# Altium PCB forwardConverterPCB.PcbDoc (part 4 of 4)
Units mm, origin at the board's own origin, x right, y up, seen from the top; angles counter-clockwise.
Board outline 382.81 x 370.12 mm, 8 copper layers (L1, L2 (GND), L3, L4, L5(GND), L6, L7 (GND), L8), stack 1.028 mm thick; 352 components, 187 nets, 1188 pads, 1016 vias.
Unrouted connection lines stored in the file: 19.
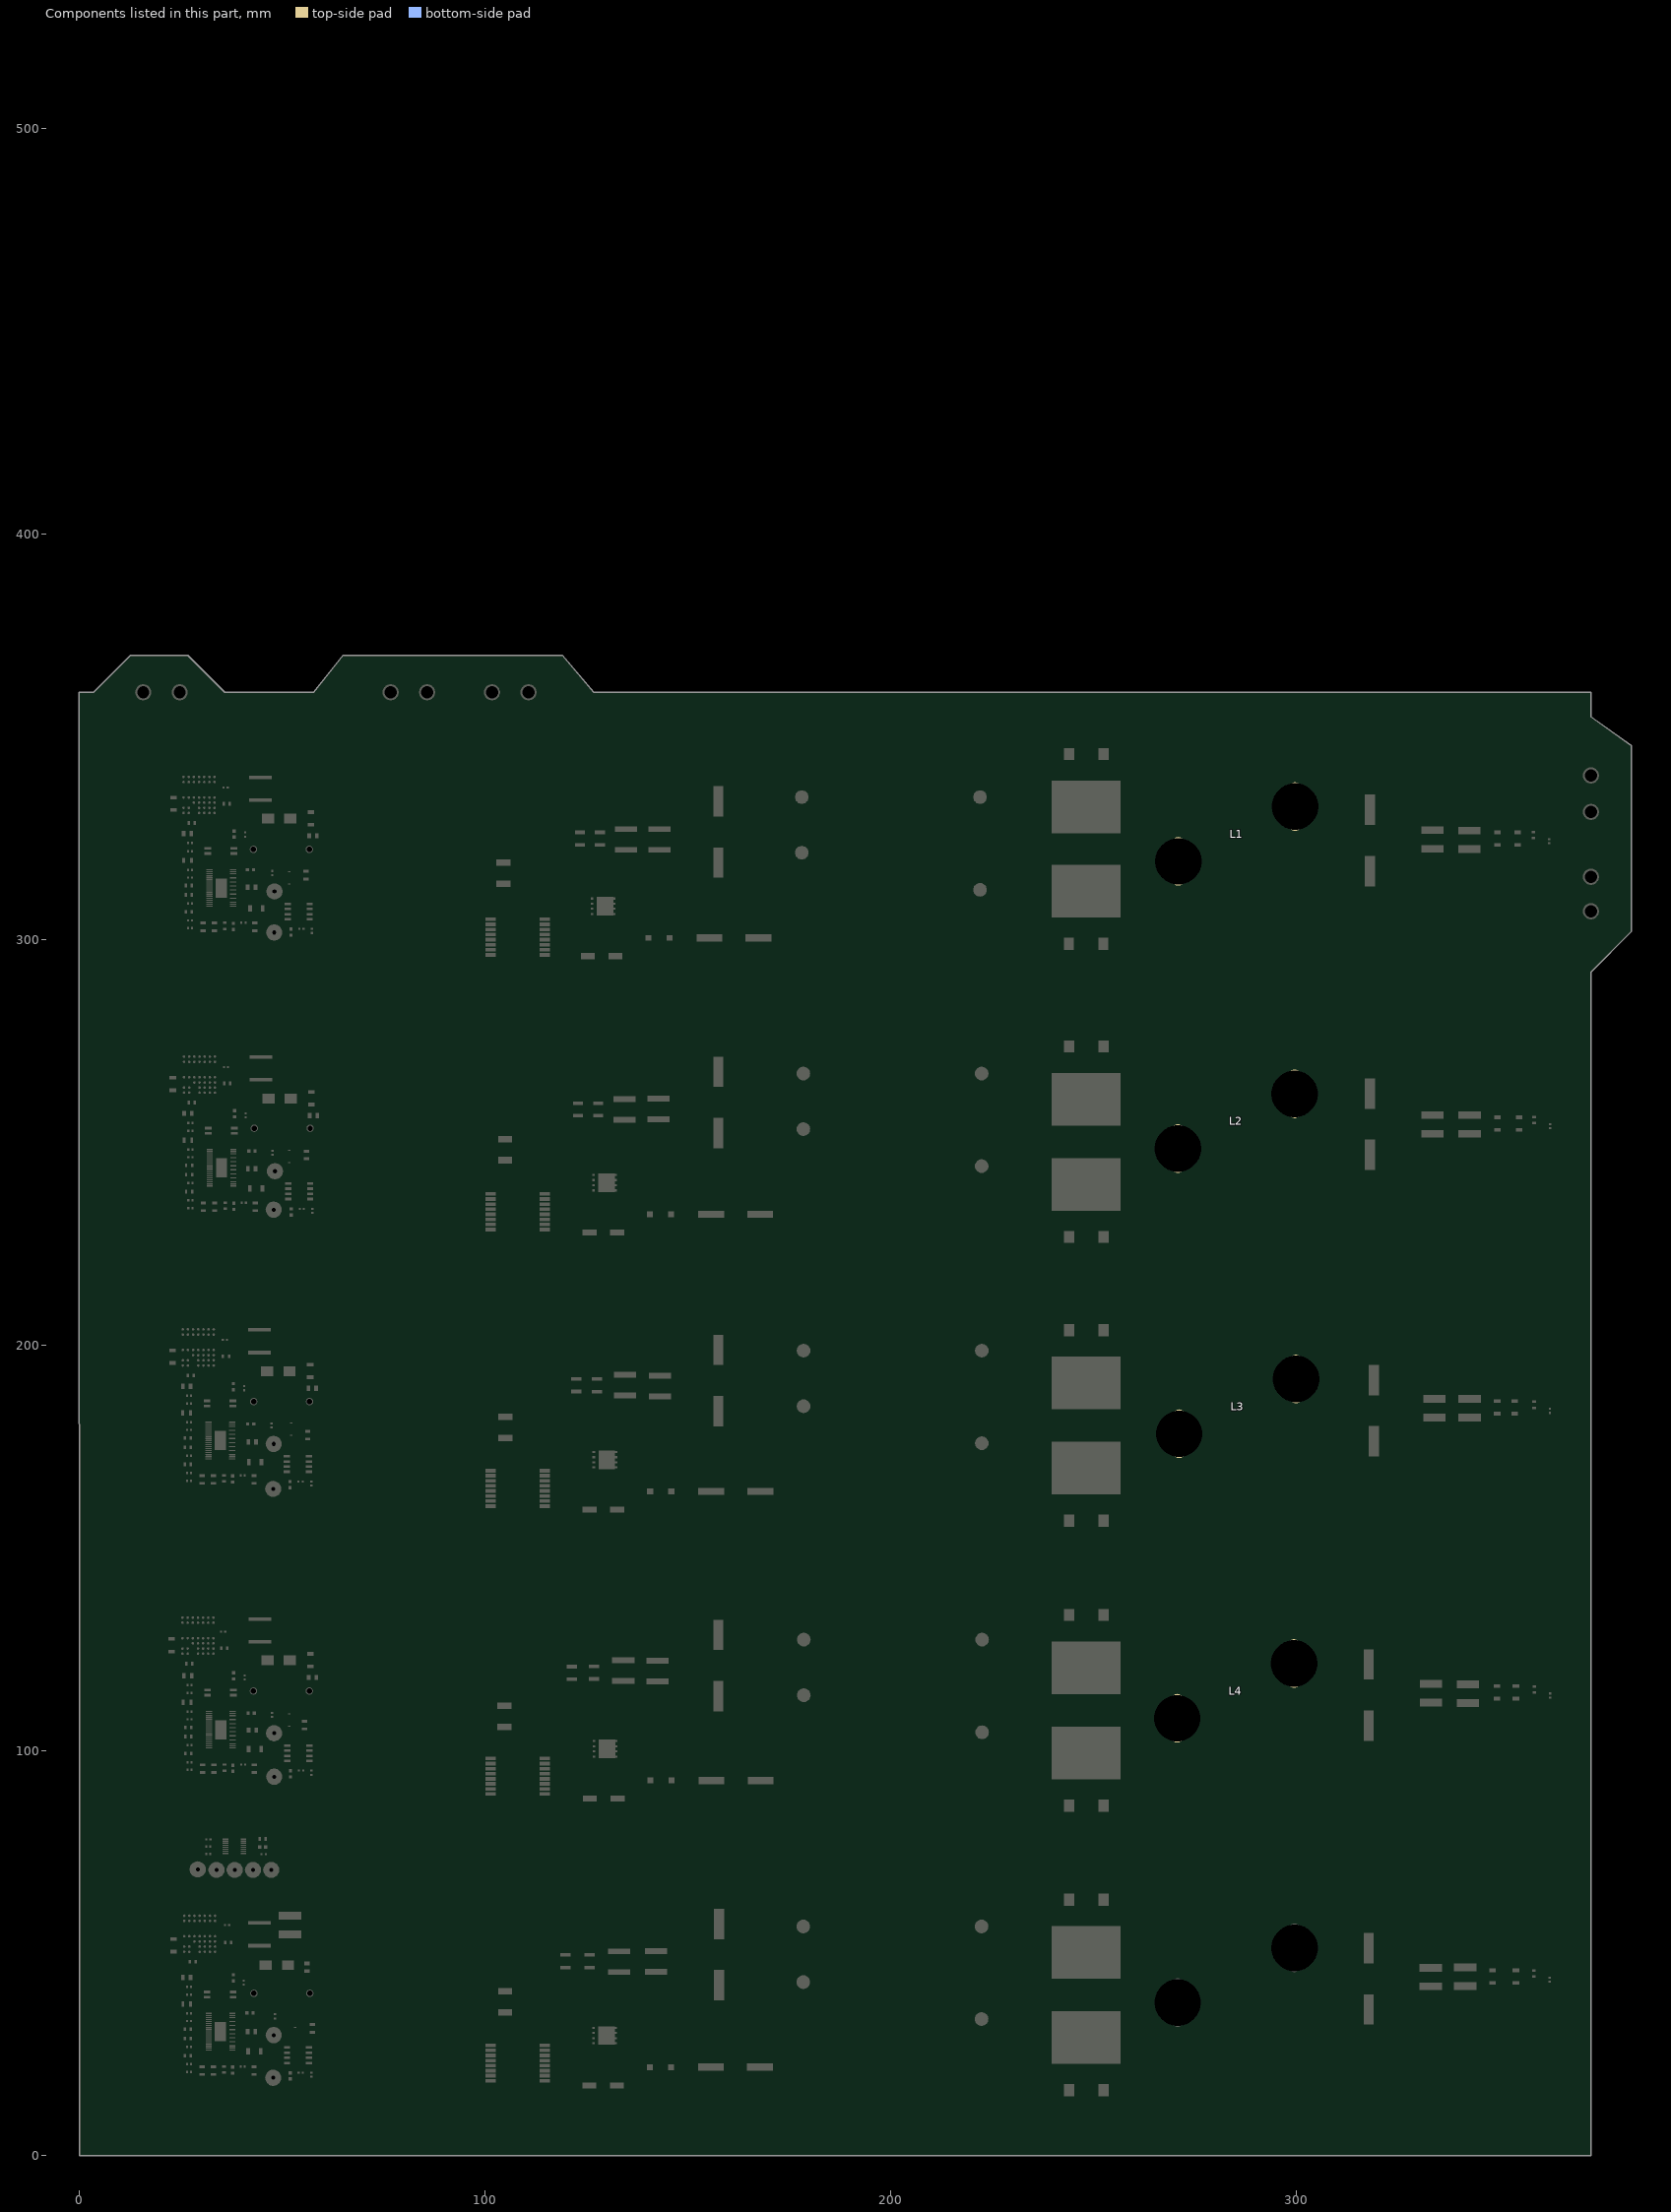
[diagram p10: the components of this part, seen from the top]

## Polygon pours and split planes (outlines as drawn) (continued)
NetNMOS2_1 on L1 "NETNMOS2_1_L01_P316" (solid, pour order 316): 97.95,245.75 99.2,247 109.2,247 110.2,245.75 106.688,235.744 106.688,229.794 105.888,228.994 98.962,228.994 97.95,230.006
NetC23_2 on L1 "NETC23_2_L01_P277" (solid, pour order 277): 31.452,340.273 31.802,340.623 33.452,340.623 33.777,340.223 33.777,338.648 33.452,338.323 31.802,338.323 31.452,338.673
no net on L1 "NONET_L01_P271" (solid, pour order 271): 103.577,330.723 103.077,330.723
NetC121_1 on L1 "NETC121_1_L01_P269" (solid, pour order 269): 143.196,26.318 143.946,27.068 159.446,27.068 160.196,26.318 160.196,17.318 159.446,16.568 143.946,16.568 143.196,17.318
NetC11_1 on L1 "NETC11_1_L01_P265" (solid, pour order 265): 142.825,304.875 143.575,305.625 159.075,305.625 159.825,304.875 159.825,295.875 159.075,295.125 143.575,295.125 142.825,295.875
GND on L1 "L1-+PH2" (solid, pour order 352): 257.95,62.549 257.95,71.551 256.2,73.5 218,73.5 216.051,71.551 216.102,45.5 218,44.049 227.401,44.049 228.852,45.5 228.852,58.75 230.901,60.799 256.2,60.799
+PH5 on L1 "L1-+PH2" (solid, pour order 349): 257.7,132.749 257.7,142 255.95,143.898 217.75,143.898 215.852,142 215.852,115.7 217.75,114.249 227.151,114.249 228.602,115.7 228.602,128.95 230.651,130.999 255.95,130.999
+PH4 on L1 "L1-+PH2" (solid, pour order 346): 257.75,202.949 257.749,212.5 256,214.249 217.651,214.249 215.902,212.5 215.902,185.9 217.8,184.449 227.201,184.449 228.652,185.9 228.652,199.15 230.701,201.199 256,201.199
+PH3 on L1 "L1-+PH2" (solid, pour order 344): 257.95,273.049 257.95,283.651 255.95,285.55 218,285.55 216.102,283.651 216.102,256 218,254.549 227.401,254.549 228.852,256 228.852,269.25 230.901,271.299 256.2,271.299
+PH2 on L1 "L1-+PH2" (solid, pour order 321): 257.95,345.25 257.95,353.901 255.95,355.8 218,355.8 216.102,353.901 216.2,326 217.7,324.5 227.45,324.5 228.7,326 228.852,341.152 230.95,343.25 255.95,343.25
NetD1_1 on L1 "L1-+PH2" (solid, pour order 320): 257.7,299.75 257.7,291.099 255.7,289.2 217.75,289.2 215.852,291.099 215.852,319.25 217.75,321.148 227.2,321.148 228.649,319.699 228.602,303.848 230.7,301.75 255.7,301.75
NetD17_1 on L1 "L1-+PH2" (solid, pour order 303): 257.85,17 257.85,8.349 255.85,6.45 217.9,6.45 216.002,8.349 216.002,38.848 218.002,40.848 227.2,40.848 228.752,39.296 228.752,21.098 230.85,19 255.85,19
NetD13_1 on L1 "L1-+PH2" (solid, pour order 302): 257.6,87.2 257.6,78.549 255.6,76.65 217.65,76.65 215.752,78.549 215.752,109.048 217.752,111.048 226.95,111.048 228.502,109.496 228.502,91.298 230.6,89.2 255.6,89.2
NetD9_1 on L1 "L1-+PH2" (solid, pour order 301): 257.65,157.4 257.65,148.749 255.65,146.85 217.7,146.85 215.802,148.749 215.802,179.248 217.802,181.248 227,181.248 228.552,179.696 228.552,161.498 230.65,159.4 255.65,159.4
NetD5_1 on L1 "L1-+PH2" (solid, pour order 300): 257.85,227.5 257.85,219.129 255.85,217.129 218.002,217.129 216.002,219.129 216.002,249.348 218.002,251.348 227.2,251.348 228.752,249.796 228.752,231.598 230.85,229.5 255.85,229.5
GND on L3 "L1-NetC2_1" (solid, pour order 1176): 296.696,23.648 281.161,23.405 275.28,17.686 275.28,2.233 277.475,0.537 364.35,0.537 365.95,2.137 365.95,41.238 363.946,43.242 298.7,43.242 296.696,41.238
+PH5 on L3 "L1-+PH5" (solid, pour order 1159): 296.525,47.408 298.704,45.229 363.696,45.229 365.7,47.233 365.7,111.174 363.696,113.178 363.641,113.178 363.573,113.246 298.327,113.246 296.525,111.444
+PH4 on L3 "L1-+PH4" (solid, pour order 1158): 346.834,115.229 363.702,115.108 365.706,117.112 365.706,181.485 363.702,183.49 347.702,183.49 347.7,183.487 298.2,183.487 296.196,181.483 296.196,165.483 296.196,117.36 298.327,115.229
+PH3 on L3 "L1-+PH3" (solid, pour order 1157): 346.016,185.483 363.452,185.358 365.456,187.363 365.456,251.735 363.452,253.74 298.202,253.74 296.198,251.735 296.198,235.735 296.198,203.49 296.196,203.488 296.196,187.487 298.2,185.483
+PH2 on L3 "L1-+PH2 1" (solid, pour order 1156): 363.446,255.608 363.452,255.608 365.456,257.612 365.456,321.985 363.452,323.99 363.448,323.99 298.202,323.99 296.198,321.985 296.198,305.985 296.197,273.614 296.196,273.613 296.196,257.612 298.2,255.608
NetC2_1 on L3 "L1-NetC2_1" (solid, pour order 1154): 296.196,327.863 298.2,325.858 373.696,325.858 375.7,327.863 375.7,345.417 365.425,355.692 298.2,355.692 296.196,353.687
NetD17_4 on L3 "NETD17_4_L03_P1129" (solid, pour order 1129): 236.138,56.376 238.15,58.387 271.624,58.387 274.099,56.376 274.099,23.683 271.624,21.382 237.844,21.382 236.138,23.088
NetD13_4 on L3 "NETD13_4_L03_P1128" (solid, pour order 1128): 235.888,126.576 237.9,128.587 271.374,128.587 273.849,126.576 273.849,93.883 271.374,91.582 237.594,91.582 235.888,93.287
NetD9_4 on L3 "NETD9_4_L03_P1127" (solid, pour order 1127): 235.938,196.776 237.95,198.787 271.424,198.787 273.899,196.776 273.899,164.083 271.424,161.782 237.644,161.782 235.938,163.487
NetD5_4 on L3 "NETD5_4_L03_P1126" (solid, pour order 1126): 236.139,266.907 238.151,268.918 271.625,268.918 274.1,266.907 274.1,234.214 271.625,231.912 237.845,231.912 236.139,233.618
NetD1_4 on L3 "NETD1_4_L03_P1125" (solid, pour order 1125): 235.914,339.082 237.926,341.093 271.4,341.093 273.875,339.082 273.875,306.389 271.4,304.087 237.62,304.087 235.914,305.793
GND on L3 "GND_L03_P623" (solid, pour order 623): 98.115,188.138 99.115,189.138 169.4,189.138 170.265,188.138 170.265,182.32 166.365,177.37 127.946,177.383 127.254,176.692 127.254,170.351 126.994,169.991 123.232,169.991 114.982,180.37 99.115,180.37 98.115,181.37
NetC121_2 on L3 "L3-NetC121_2" (solid, pour order 1101): 19 vertices, not listed, extent 111.208,8.056 182.283,45.406
NetC98_2 on L3 "L3-NetC98_2" (solid, pour order 1099): 19 vertices, not listed, extent 111.336,78.79 182.411,116.14
NetC75_2 on L3 "L3-NetC75_2" (solid, pour order 1097): 19 vertices, not listed, extent 111.282,150.079 182.357,187.429
NetC52_2 on L3 "L3-NetC52_2" (solid, pour order 1095): 19 vertices, not listed, extent 111.223,218.427 182.298,255.777
NetC11_2 on L3 "L3-NetC11_2" (solid, pour order 1093): 19 vertices, not listed, extent 110.839,286.61 181.914,323.96
+12V on L3 "L1-+12V" (solid, pour order 1061): 51 vertices, not listed, extent 5.95,5.219 27.7,364.487
Vin on L3 "L1-No Net" (solid, pour order 1060): 49 vertices, not listed, extent 65.009,5.28 186.969,364.487
GND on L3 "GND_L03_P624" (solid, pour order 624): 98.365,256.137 99.365,257.137 169.65,257.137 170.515,256.137 170.515,250.32 166.615,245.37 128.196,245.383 127.504,244.692 127.504,238.351 127.244,237.991 123.482,237.991 115.232,248.37 99.365,248.37 98.365,249.37
GND on L3 "GND_L03_P622" (solid, pour order 622): 98.115,117.138 99.115,118.138 169.4,118.138 170.265,117.138 170.265,111.32 166.365,106.37 127.946,106.383 127.254,105.692 127.254,99.351 126.994,98.991 123.232,98.991 114.982,109.37 99.115,109.37 98.115,110.37
GND on L3 "GND_L03_P621" (solid, pour order 621): 98.115,46.387 99.115,47.387 169.4,47.387 170.265,46.387 170.265,40.57 166.365,35.62 127.946,35.633 127.254,34.942 127.254,28.601 126.994,28.241 123.232,28.241 114.982,38.62 99.115,38.62 98.115,39.62
NetC122_1 on L3 "NETC122_1_L03_P620" (solid, pour order 620): 127.669,32.806 128.269,33.556 134.696,33.556 141.446,33.556 142.196,32.806 142.196,24.556 142.196,15.806 141.696,15.306 130.696,15.306 130.196,15.806 130.196,17.806 130.196,22.056 127.669,25.533
NetC99_1 on L3 "NETC99_1_L03_P619" (solid, pour order 619): 127.797,103.54 128.397,104.29 134.824,104.29 141.574,104.29 142.324,103.54 142.324,95.29 142.324,86.54 141.824,86.04 130.824,86.04 130.324,86.54 130.324,88.54 130.324,92.79 127.797,96.268
NetC98_1 on L3 "NETC98_1_L03_P618" (solid, pour order 618): 143.324,97.04 144.074,97.79 159.574,97.79 160.324,97.04 160.324,88.04 159.574,87.29 144.074,87.29 143.324,88.04
NetC76_1 on L3 "NETC76_1_L03_P617" (solid, pour order 617): 127.743,174.829 128.343,175.579 134.77,175.579 141.52,175.579 142.27,174.829 142.27,166.579 142.27,157.829 141.77,157.329 130.77,157.329 130.27,157.829 130.27,159.829 130.27,164.079 127.743,167.557
NetC75_1 on L3 "NETC75_1_L03_P616" (solid, pour order 616): 143.27,168.329 144.02,169.079 159.52,169.079 160.27,168.329 160.27,159.329 159.52,158.579 144.02,158.579 143.27,159.329
NetC53_1 on L3 "NETC53_1_L03_P615" (solid, pour order 615): 127.684,243.177 128.284,243.927 134.711,243.927 141.461,243.927 142.211,243.177 142.211,234.927 142.211,226.177 141.711,225.677 130.711,225.677 130.211,226.177 130.211,228.177 130.211,232.427 127.684,235.905
NetC52_1 on L3 "NETC52_1_L03_P609" (solid, pour order 609): 143.211,236.677 143.961,237.427 159.461,237.427 160.211,236.677 160.211,227.677 159.461,226.927 143.961,226.927 143.211,227.677
NetNMOS5_1 on L3 "NETNMOS5_1_L03_P596" (solid, pour order 596): 97.7,35.987 98.95,37.237 108.95,37.237 109.95,35.987 106.437,25.981 106.437,20.031 105.638,19.231 98.712,19.231 97.7,20.244
NetNMOS4_1 on L3 "NETNMOS4_1_L03_P595" (solid, pour order 595): 97.7,106.738 98.95,107.987 108.95,107.987 109.95,106.738 106.437,96.731 106.437,90.781 105.638,89.981 98.712,89.981 97.7,90.994
NetNMOS3_1 on L3 "NETNMOS3_1_L03_P594" (solid, pour order 594): 97.7,177.738 98.95,178.987 108.95,178.987 109.95,177.738 106.437,167.731 106.437,161.781 105.638,160.981 98.712,160.981 97.7,161.994
NetNMOS2_1 on L3 "NETNMOS2_1_L03_P593" (solid, pour order 593): 97.95,245.737 99.2,246.987 109.2,246.987 110.2,245.737 106.687,235.731 106.687,229.781 105.888,228.981 98.962,228.981 97.95,229.994
GND on L3 "GND_L03_P582" (solid, pour order 582): 97.769,323.275 98.769,324.275 168.919,324.275 169.919,323.275 169.919,319.225 166.019,314.275 127.6,314.287 126.909,313.596 126.909,307.255 126.649,306.895 122.886,306.895 114.636,317.275 98.769,317.275 97.769,318.275
NetC12_1 on L3 "NETC12_1_L03_P581" (solid, pour order 581): 127.3,311.36 127.9,312.11 134.327,312.11 141.077,312.11 141.827,311.36 141.827,303.11 141.827,294.36 141.327,293.86 130.327,293.86 129.827,294.36 129.827,296.36 129.827,300.61 127.3,304.087
no net on L3 "NONET_L03_P575" (solid, pour order 575): 103.577,330.71 103.077,330.71
NetC121_1 on L3 "NETC121_1_L03_P573" (solid, pour order 573): 143.196,26.306 143.946,27.056 159.446,27.056 160.196,26.306 160.196,17.306 159.446,16.556 143.946,16.556 143.196,17.306
NetC11_1 on L3 "NETC11_1_L03_P572" (solid, pour order 572): 142.827,304.86 143.577,305.61 159.077,305.61 159.827,304.86 159.827,295.86 159.077,295.11 143.577,295.11 142.827,295.86
NetNMOS1_1 on L3 "NETNMOS1_1_L03_P571" (solid, pour order 571): 97.95,313.738 99.2,314.987 109.2,314.987 110.2,313.738 106.687,303.731 106.687,297.781 105.888,296.981 98.962,296.981 97.95,297.994
GND on L3 "L1-+PH2" (solid, pour order 604): 257.95,62.537 257.95,71.538 256.2,73.487 218,73.487 216.051,71.538 216.102,45.487 218,44.037 227.401,44.037 228.852,45.487 228.852,58.737 230.901,60.787 256.2,60.787
+PH5 on L3 "L1-+PH2" (solid, pour order 603): 257.7,132.737 257.7,141.987 255.95,143.886 217.75,143.886 215.852,141.987 215.852,115.688 217.75,114.237 227.151,114.237 228.602,115.688 228.602,128.937 230.651,130.987 255.95,130.987
+PH4 on L3 "L1-+PH2" (solid, pour order 602): 257.75,202.937 257.749,212.487 256,214.236 217.651,214.236 215.902,212.487 215.902,185.887 217.8,184.437 227.201,184.437 228.652,185.887 228.652,199.137 230.701,201.187 256,201.187
+PH3 on L3 "L1-+PH2" (solid, pour order 601): 257.95,273.037 257.95,283.639 255.95,285.537 218,285.537 216.102,283.639 216.102,255.987 218,254.537 227.401,254.537 228.852,255.987 228.852,269.237 230.901,271.287 256.2,271.287
+PH2 on L3 "L1-+PH2" (solid, pour order 598): 257.95,345.237 257.95,353.889 255.95,355.787 218,355.787 216.102,353.889 216.2,325.987 217.7,324.487 227.45,324.487 228.7,325.987 228.852,341.139 230.95,343.237 255.95,343.237
NetD1_1 on L3 "L1-+PH2" (solid, pour order 597): 257.7,299.738 257.7,291.086 255.7,289.188 217.75,289.188 215.852,291.086 215.852,319.237 217.75,321.136 227.2,321.136 228.649,319.687 228.602,303.836 230.7,301.737 255.7,301.737
NetD17_1 on L3 "L1-+PH2" (solid, pour order 592): 257.85,16.987 257.85,8.336 255.85,6.438 217.9,6.438 216.002,8.336 216.002,38.835 218.002,40.835 227.2,40.835 228.752,39.284 228.752,21.086 230.85,18.987 255.85,18.987
NetD13_1 on L3 "L1-+PH2" (solid, pour order 591): 257.6,87.187 257.6,78.536 255.6,76.638 217.65,76.638 215.752,78.536 215.752,109.035 217.752,111.035 226.95,111.035 228.502,109.484 228.502,91.286 230.6,89.187 255.6,89.187
NetD9_1 on L3 "L1-+PH2" (solid, pour order 590): 257.65,157.387 257.65,148.736 255.65,146.838 217.7,146.838 215.802,148.736 215.802,179.235 217.802,181.235 227,181.235 228.552,179.684 228.552,161.486 230.65,159.387 255.65,159.387
NetD5_1 on L3 "L1-+PH2" (solid, pour order 589): 257.85,227.487 257.85,219.117 255.85,217.117 218.002,217.117 216.002,219.117 216.002,249.335 218.002,251.335 227.2,251.335 228.752,249.784 228.752,231.586 230.85,229.487 255.85,229.487
GND on L4 "L1-NetC2_1" (solid, pour order 1177): 296.696,23.648 281.161,23.405 275.28,17.686 275.28,2.233 277.475,0.537 364.35,0.537 365.95,2.137 365.95,41.238 363.946,43.242 298.7,43.242 296.696,41.238
+PH5 on L4 "L1-+PH5" (solid, pour order 1165): 296.525,47.408 298.704,45.229 363.696,45.229 365.7,47.233 365.7,111.174 363.696,113.178 363.641,113.178 363.573,113.246 298.327,113.246 296.525,111.444
+PH4 on L4 "L1-+PH4" (solid, pour order 1164): 346.834,115.229 363.702,115.108 365.706,117.112 365.706,181.485 363.702,183.49 347.702,183.49 347.7,183.487 298.2,183.487 296.196,181.483 296.196,165.483 296.196,117.36 298.327,115.229
+PH3 on L4 "L1-+PH3" (solid, pour order 1163): 346.016,185.483 363.452,185.358 365.456,187.363 365.456,251.735 363.452,253.74 298.202,253.74 296.198,251.735 296.198,235.735 296.198,203.49 296.196,203.488 296.196,187.487 298.2,185.483
+PH2 on L4 "L1-+PH2 1" (solid, pour order 1162): 363.446,255.608 363.452,255.608 365.456,257.612 365.456,321.985 363.452,323.99 363.448,323.99 298.202,323.99 296.198,321.985 296.198,305.985 296.197,273.614 296.196,273.613 296.196,257.612 298.2,255.608
NetC2_1 on L4 "L1-NetC2_1" (solid, pour order 1160): 296.196,327.863 298.2,325.858 373.696,325.858 375.7,327.863 375.7,345.417 365.425,355.692 298.2,355.692 296.196,353.687
NetD17_4 on L4 "NETD17_4_L04_P1134" (solid, pour order 1134): 236.138,56.376 238.15,58.387 271.624,58.387 274.099,56.376 274.099,23.683 271.624,21.382 237.844,21.382 236.138,23.088
NetD13_4 on L4 "NETD13_4_L04_P1133" (solid, pour order 1133): 235.888,126.576 237.9,128.587 271.374,128.587 273.849,126.576 273.849,93.883 271.374,91.582 237.594,91.582 235.888,93.287
NetD9_4 on L4 "NETD9_4_L04_P1132" (solid, pour order 1132): 235.938,196.776 237.95,198.787 271.424,198.787 273.899,196.776 273.899,164.083 271.424,161.782 237.644,161.782 235.938,163.487
NetD5_4 on L4 "NETD5_4_L04_P1131" (solid, pour order 1131): 236.139,266.907 238.151,268.918 271.625,268.918 274.1,266.907 274.1,234.214 271.625,231.912 237.845,231.912 236.139,233.618
NetD1_4 on L4 "NETD1_4_L04_P1130" (solid, pour order 1130): 235.914,339.082 237.926,341.093 271.4,341.093 273.875,339.082 273.875,306.389 271.4,304.087 237.62,304.087 235.914,305.793
GND on L4 "GND_L04_P839" (solid, pour order 839): 98.115,188.138 99.115,189.138 169.4,189.138 170.265,188.138 170.265,182.32 166.365,177.37 127.946,177.383 127.254,176.692 127.254,170.351 126.994,169.991 123.232,169.991 114.982,180.37 99.115,180.37 98.115,181.37
NetC121_2 on L4 "L4-NetC121_2" (solid, pour order 1111): 19 vertices, not listed, extent 111.208,8.056 182.283,45.406
NetC98_2 on L4 "L4-NetC98_2" (solid, pour order 1109): 19 vertices, not listed, extent 111.336,78.79 182.411,116.14
NetC75_2 on L4 "L4-NetC75_2" (solid, pour order 1107): 19 vertices, not listed, extent 111.282,150.079 182.357,187.429
NetC52_2 on L4 "L4-NetC52_2" (solid, pour order 1105): 19 vertices, not listed, extent 111.223,218.427 182.298,255.777
NetC11_2 on L4 "L4-NetC11_2" (solid, pour order 1103): 19 vertices, not listed, extent 110.839,286.61 181.914,323.96
+12V on L4 "L1-+12V" (solid, pour order 1063): 51 vertices, not listed, extent 5.95,5.219 27.7,364.487
Vin on L4 "L1-No Net" (solid, pour order 1062): 49 vertices, not listed, extent 65.009,5.28 186.969,364.487
GND on L4 "GND_L04_P840" (solid, pour order 840): 98.365,256.137 99.365,257.137 169.65,257.137 170.515,256.137 170.515,250.32 166.615,245.37 128.196,245.383 127.504,244.692 127.504,238.351 127.244,237.991 123.482,237.991 115.232,248.37 99.365,248.37 98.365,249.37
GND on L4 "GND_L04_P838" (solid, pour order 838): 98.115,117.138 99.115,118.138 169.4,118.138 170.265,117.138 170.265,111.32 166.365,106.37 127.946,106.383 127.254,105.692 127.254,99.351 126.994,98.991 123.232,98.991 114.982,109.37 99.115,109.37 98.115,110.37
GND on L4 "GND_L04_P837" (solid, pour order 837): 98.115,46.387 99.115,47.387 169.4,47.387 170.265,46.387 170.265,40.57 166.365,35.62 127.946,35.633 127.254,34.942 127.254,28.601 126.994,28.241 123.232,28.241 114.982,38.62 99.115,38.62 98.115,39.62
NetC122_1 on L4 "NETC122_1_L04_P836" (solid, pour order 836): 127.669,32.806 128.269,33.556 134.696,33.556 141.446,33.556 142.196,32.806 142.196,24.556 142.196,15.806 141.696,15.306 130.696,15.306 130.196,15.806 130.196,17.806 130.196,22.056 127.669,25.533
NetC99_1 on L4 "NETC99_1_L04_P835" (solid, pour order 835): 127.797,103.54 128.397,104.29 134.824,104.29 141.574,104.29 142.324,103.54 142.324,95.29 142.324,86.54 141.824,86.04 130.824,86.04 130.324,86.54 130.324,88.54 130.324,92.79 127.797,96.268
NetC98_1 on L4 "NETC98_1_L04_P834" (solid, pour order 834): 143.324,97.04 144.074,97.79 159.574,97.79 160.324,97.04 160.324,88.04 159.574,87.29 144.074,87.29 143.324,88.04
NetC76_1 on L4 "NETC76_1_L04_P833" (solid, pour order 833): 127.743,174.829 128.343,175.579 134.77,175.579 141.52,175.579 142.27,174.829 142.27,166.579 142.27,157.829 141.77,157.329 130.77,157.329 130.27,157.829 130.27,159.829 130.27,164.079 127.743,167.557
NetC75_1 on L4 "NETC75_1_L04_P832" (solid, pour order 832): 143.27,168.329 144.02,169.079 159.52,169.079 160.27,168.329 160.27,159.329 159.52,158.579 144.02,158.579 143.27,159.329
NetC53_1 on L4 "NETC53_1_L04_P831" (solid, pour order 831): 127.684,243.177 128.284,243.927 134.711,243.927 141.461,243.927 142.211,243.177 142.211,234.927 142.211,226.177 141.711,225.677 130.711,225.677 130.211,226.177 130.211,228.177 130.211,232.427 127.684,235.905
NetC52_1 on L4 "NETC52_1_L04_P825" (solid, pour order 825): 143.211,236.677 143.961,237.427 159.461,237.427 160.211,236.677 160.211,227.677 159.461,226.927 143.961,226.927 143.211,227.677
NetNMOS5_1 on L4 "NETNMOS5_1_L04_P812" (solid, pour order 812): 97.7,35.987 98.95,37.237 108.95,37.237 109.95,35.987 106.437,25.981 106.437,20.031 105.638,19.231 98.712,19.231 97.7,20.244
NetNMOS4_1 on L4 "NETNMOS4_1_L04_P811" (solid, pour order 811): 97.7,106.738 98.95,107.987 108.95,107.987 109.95,106.738 106.437,96.731 106.437,90.781 105.638,89.981 98.712,89.981 97.7,90.994
NetNMOS3_1 on L4 "NETNMOS3_1_L04_P810" (solid, pour order 810): 97.7,177.738 98.95,178.987 108.95,178.987 109.95,177.738 106.437,167.731 106.437,161.781 105.638,160.981 98.712,160.981 97.7,161.994
NetNMOS2_1 on L4 "NETNMOS2_1_L04_P809" (solid, pour order 809): 97.95,245.737 99.2,246.987 109.2,246.987 110.2,245.737 106.687,235.731 106.687,229.781 105.888,228.981 98.962,228.981 97.95,229.994
GND on L4 "GND_L04_P798" (solid, pour order 798): 97.769,323.275 98.769,324.275 168.919,324.275 169.919,323.275 169.919,319.225 166.019,314.275 127.6,314.287 126.909,313.596 126.909,307.255 126.649,306.895 122.886,306.895 114.636,317.275 98.769,317.275 97.769,318.275
NetC12_1 on L4 "NETC12_1_L04_P797" (solid, pour order 797): 127.3,311.36 127.9,312.11 134.327,312.11 141.077,312.11 141.827,311.36 141.827,303.11 141.827,294.36 141.327,293.86 130.327,293.86 129.827,294.36 129.827,296.36 129.827,300.61 127.3,304.087
no net on L4 "NONET_L04_P791" (solid, pour order 791): 103.577,330.71 103.077,330.71
NetC121_1 on L4 "NETC121_1_L04_P789" (solid, pour order 789): 143.196,26.306 143.946,27.056 159.446,27.056 160.196,26.306 160.196,17.306 159.446,16.556 143.946,16.556 143.196,17.306
NetC11_1 on L4 "NETC11_1_L04_P788" (solid, pour order 788): 142.827,304.86 143.577,305.61 159.077,305.61 159.827,304.86 159.827,295.86 159.077,295.11 143.577,295.11 142.827,295.86
NetNMOS1_1 on L4 "NETNMOS1_1_L04_P787" (solid, pour order 787): 97.95,313.738 99.2,314.987 109.2,314.987 110.2,313.738 106.687,303.731 106.687,297.781 105.888,296.981 98.962,296.981 97.95,297.994
GND on L4 "L1-+PH2" (solid, pour order 820): 257.95,62.537 257.95,71.538 256.2,73.487 218,73.487 216.051,71.538 216.102,45.487 218,44.037 227.401,44.037 228.852,45.487 228.852,58.737 230.901,60.787 256.2,60.787
+PH5 on L4 "L1-+PH2" (solid, pour order 819): 257.7,132.737 257.7,141.987 255.95,143.886 217.75,143.886 215.852,141.987 215.852,115.688 217.75,114.237 227.151,114.237 228.602,115.688 228.602,128.937 230.651,130.987 255.95,130.987
+PH4 on L4 "L1-+PH2" (solid, pour order 818): 257.75,202.937 257.749,212.487 256,214.236 217.651,214.236 215.902,212.487 215.902,185.887 217.8,184.437 227.201,184.437 228.652,185.887 228.652,199.137 230.701,201.187 256,201.187
+PH3 on L4 "L1-+PH2" (solid, pour order 817): 257.95,273.037 257.95,283.639 255.95,285.537 218,285.537 216.102,283.639 216.102,255.987 218,254.537 227.401,254.537 228.852,255.987 228.852,269.237 230.901,271.287 256.2,271.287
+PH2 on L4 "L1-+PH2" (solid, pour order 814): 257.95,345.237 257.95,353.889 255.95,355.787 218,355.787 216.102,353.889 216.2,325.987 217.7,324.487 227.45,324.487 228.7,325.987 228.852,341.139 230.95,343.237 255.95,343.237
NetD1_1 on L4 "L1-+PH2" (solid, pour order 813): 257.7,299.738 257.7,291.086 255.7,289.188 217.75,289.188 215.852,291.086 215.852,319.237 217.75,321.136 227.2,321.136 228.649,319.687 228.602,303.836 230.7,301.737 255.7,301.737
NetD17_1 on L4 "L1-+PH2" (solid, pour order 808): 257.85,16.987 257.85,8.336 255.85,6.438 217.9,6.438 216.002,8.336 216.002,38.835 218.002,40.835 227.2,40.835 228.752,39.284 228.752,21.086 230.85,18.987 255.85,18.987
NetD13_1 on L4 "L1-+PH2" (solid, pour order 807): 257.6,87.187 257.6,78.536 255.6,76.638 217.65,76.638 215.752,78.536 215.752,109.035 217.752,111.035 226.95,111.035 228.502,109.484 228.502,91.286 230.6,89.187 255.6,89.187
NetD9_1 on L4 "L1-+PH2" (solid, pour order 806): 257.65,157.387 257.65,148.736 255.65,146.838 217.7,146.838 215.802,148.736 215.802,179.235 217.802,181.235 227,181.235 228.552,179.684 228.552,161.486 230.65,159.387 255.65,159.387
NetD5_1 on L4 "L1-+PH2" (solid, pour order 805): 257.85,227.487 257.85,219.117 255.85,217.117 218.002,217.117 216.002,219.117 216.002,249.335 218.002,251.335 227.2,251.335 228.752,249.784 228.752,231.586 230.85,229.487 255.85,229.487
NetD17_4 on L6 "NETD17_4_L06_P1188" (solid, pour order 1188): 235.727,56.444 237.738,58.455 271.213,58.455 273.688,56.444 273.688,23.751 271.213,21.449 237.433,21.449 235.727,23.155
NetD13_4 on L6 "NETD13_4_L06_P1186" (solid, pour order 1186): 235.872,126.666 237.884,128.678 271.358,128.678 273.833,126.666 273.833,93.973 271.358,91.672 237.578,91.672 235.872,93.378
NetD9_4 on L6 "NETD9_4_L06_P1185" (solid, pour order 1185): 235.897,196.791 237.909,198.803 271.383,198.803 273.858,196.791 273.858,164.098 271.383,161.797 237.603,161.797 235.897,163.503
NetD5_4 on L6 "NETD5_4_L06_P1184" (solid, pour order 1184): 236.122,266.916 238.134,268.928 271.608,268.928 274.083,266.916 274.083,234.223 271.608,231.922 237.828,231.922 236.122,233.628
NetD1_4 on L6 "NETD1_4_L06_P1182" (solid, pour order 1182): 235.922,339.091 237.934,341.103 271.408,341.103 273.883,339.091 273.883,306.398 271.408,304.097 237.628,304.097 235.922,305.803
NetC2_1 on L6 "L1-NetC2_1" (solid, pour order 1179): 296.198,327.873 298.202,325.869 373.698,325.869 375.702,327.873 375.702,345.427 365.427,355.702 298.202,355.702 296.198,353.698
+PH5 on L6 "L5-+PH2" (solid, pour order 1137): 26 vertices, not listed, extent 216.012,45.175 365.7,145.375
GND on L6 "L5-+PH2" (solid, pour order 1138): 23 vertices, not listed, extent 216.154,1.167 365.507,75.312
+PH2 on L6 "L5-+PH2" (solid, pour order 1003): 26 vertices, not listed, extent 215.95,255.519 365.304,355.698
+PH4 on L6 "L5-+PH2" (solid, pour order 1136): 25 vertices, not listed, extent 216.229,115.248 365.583,215.427
+PH3 on L6 "L5-+PH2" (solid, pour order 1135): 26 vertices, not listed, extent 216.102,185.45 365.456,285.629
NetD1_1 on L6 "L1-+PH2" (solid, pour order 867): 257.7,299.738 257.7,291.086 255.7,289.188 217.75,289.188 215.852,291.086 215.852,319.237 217.75,321.136 227.2,321.136 228.649,319.687 228.602,303.836 230.7,301.737 255.7,301.737
NetD17_1 on L6 "L1-+PH2" (solid, pour order 862): 257.85,16.987 257.85,8.336 255.85,6.438 217.9,6.438 216.002,8.336 216.002,38.835 218.002,40.835 227.2,40.835 228.752,39.284 228.752,21.086 230.85,18.987 255.85,18.987
NetD13_1 on L6 "L1-+PH2" (solid, pour order 861): 257.6,87.187 257.6,78.536 255.6,76.638 217.65,76.638 215.752,78.536 215.752,109.035 217.752,111.035 226.95,111.035 228.502,109.484 228.502,91.286 230.6,89.187 255.6,89.187
NetD9_1 on L6 "L1-+PH2" (solid, pour order 860): 257.65,157.387 257.65,148.736 255.65,146.838 217.7,146.838 215.802,148.736 215.802,179.235 217.802,181.235 227,181.235 228.552,179.684 228.552,161.486 230.65,159.387 255.65,159.387
NetD5_1 on L6 "L1-+PH2" (solid, pour order 859): 257.85,227.487 257.85,219.117 255.85,217.117 218.002,217.117 216.002,219.117 216.002,249.335 218.002,251.335 227.2,251.335 228.752,249.784 228.752,231.586 230.85,229.487 255.85,229.487
GND on L2 (GND) "GND_L02_P421" (solid, pour order 421): 34 vertices, not listed, extent 0.375,0.3 381.761,369.55
NetC2_1 on L2 (GND) "L1-NetC2_1" (solid, pour order 1178): 296.198,327.873 298.202,325.869 373.698,325.869 375.702,327.873 375.702,345.427 365.427,355.702 298.202,355.702 296.198,353.698
+PH3 on L2 (GND) "L2 (GND)-+PH2" (solid, pour order 1116): 25 vertices, not listed, extent 216.406,185.548 341.629,285.801
+PH2 on L2 (GND) "L2 (GND)-+PH2" (solid, pour order 1052): 25 vertices, not listed, extent 216.196,255.447 341.419,355.701
+PH5 on L2 (GND) "L2 (GND)-+PH2" (solid, pour order 1119): 25 vertices, not listed, extent 216.681,45.138 341.904,145.392
+PH4 on L2 (GND) "L2 (GND)-+PH2" (solid, pour order 1118): 25 vertices, not listed, extent 216.106,115.271 341.329,215.525
GND on L7 (GND) "GND_L07_P1170" (solid, pour order 1170): 34 vertices, not listed, extent 0.3,0.3 381.688,369.925
NetC2_1 on L7 (GND) "L1-NetC2_1" (solid, pour order 1180): 296.198,327.873 298.202,325.869 373.698,325.869 375.702,327.873 375.702,345.427 365.427,355.702 298.202,355.702 296.198,353.698
+PH5 on L7 (GND) "L2 (GND)-+PH2" (solid, pour order 1174): 25 vertices, not listed, extent 216.606,45.138 341.829,145.392
+PH4 on L7 (GND) "L2 (GND)-+PH2" (solid, pour order 1173): 25 vertices, not listed, extent 216.031,115.271 341.254,215.525
+PH3 on L7 (GND) "L2 (GND)-+PH2" (solid, pour order 1172): 25 vertices, not listed, extent 216.331,185.548 341.554,285.801
+PH2 on L7 (GND) "L2 (GND)-+PH2" (solid, pour order 1171): 25 vertices, not listed, extent 216.121,255.447 341.344,355.701
NetC121_2 on L8 "L4-NetC121_2" (solid, pour order 1216): 19 vertices, not listed, extent 110.959,8.123 182.034,45.473
NetC98_2 on L8 "L4-NetC98_2" (solid, pour order 1215): 19 vertices, not listed, extent 111.087,78.857 182.162,116.207
NetC75_2 on L8 "L4-NetC75_2" (solid, pour order 1214): 19 vertices, not listed, extent 111.033,150.146 182.108,187.496
NetC52_2 on L8 "L4-NetC52_2" (solid, pour order 1213): 19 vertices, not listed, extent 110.974,218.494 182.049,255.844
NetC11_2 on L8 "L4-NetC11_2" (solid, pour order 1212): 19 vertices, not listed, extent 110.59,286.677 181.665,324.027
+12V on L8 "L1-+12V" (solid, pour order 1211): 51 vertices, not listed, extent 5.701,5.286 27.451,364.555
Vin on L8 "L1-No Net" (solid, pour order 1210): 49 vertices, not listed, extent 64.76,5.347 186.72,364.555
GND on L8 "GND_L08_P1209" (solid, pour order 1209): 98.116,256.205 99.116,257.205 169.401,257.205 170.266,256.205 170.266,250.387 166.366,245.437 127.947,245.45 127.255,244.759 127.255,238.418 126.995,238.058 123.233,238.058 114.983,248.437 99.116,248.437 98.116,249.437
GND on L8 "GND_L08_P1208" (solid, pour order 1208): 97.866,188.205 98.866,189.205 169.151,189.205 170.016,188.205 170.016,182.387 166.116,177.437 127.697,177.45 127.005,176.759 127.005,170.418 126.745,170.058 122.983,170.058 114.733,180.437 98.866,180.437 97.866,181.437
GND on L8 "GND_L08_P1207" (solid, pour order 1207): 97.866,117.205 98.866,118.205 169.151,118.205 170.016,117.205 170.016,111.387 166.116,106.437 127.697,106.45 127.005,105.759 127.005,99.418 126.745,99.058 122.983,99.058 114.733,109.437 98.866,109.437 97.866,110.437
GND on L8 "GND_L08_P1206" (solid, pour order 1206): 97.866,46.455 98.866,47.455 169.151,47.455 170.016,46.455 170.016,40.637 166.116,35.687 127.697,35.7 127.005,35.009 127.005,28.668 126.745,28.308 122.983,28.308 114.733,38.687 98.866,38.687 97.866,39.687
NetC122_1 on L8 "NETC122_1_L08_P1205" (solid, pour order 1205): 127.42,32.873 128.02,33.623 134.447,33.623 141.197,33.623 141.947,32.873 141.947,24.623 141.947,15.873 141.447,15.373 130.447,15.373 129.947,15.873 129.947,17.873 129.947,22.123 127.42,25.6
NetC99_1 on L8 "NETC99_1_L08_P1204" (solid, pour order 1204): 127.548,103.607 128.148,104.357 134.575,104.357 141.325,104.357 142.075,103.607 142.075,95.357 142.075,86.607 141.575,86.107 130.575,86.107 130.075,86.607 130.075,88.607 130.075,92.857 127.548,96.335
NetC98_1 on L8 "NETC98_1_L08_P1203" (solid, pour order 1203): 143.075,97.107 143.825,97.857 159.325,97.857 160.075,97.107 160.075,88.107 159.325,87.357 143.825,87.357 143.075,88.107
NetC76_1 on L8 "NETC76_1_L08_P1202" (solid, pour order 1202): 127.494,174.896 128.094,175.646 134.521,175.646 141.271,175.646 142.021,174.896 142.021,166.646 142.021,157.896 141.521,157.396 130.521,157.396 130.021,157.896 130.021,159.896 130.021,164.146 127.494,167.624
NetC75_1 on L8 "NETC75_1_L08_P1201" (solid, pour order 1201): 143.021,168.396 143.771,169.146 159.271,169.146 160.021,168.396 160.021,159.396 159.271,158.646 143.771,158.646 143.021,159.396
NetC53_1 on L8 "NETC53_1_L08_P1200" (solid, pour order 1200): 127.435,243.244 128.035,243.994 134.462,243.994 141.212,243.994 141.962,243.244 141.962,234.994 141.962,226.244 141.462,225.744 130.462,225.744 129.962,226.244 129.962,228.244 129.962,232.494 127.435,235.972
NetC52_1 on L8 "NETC52_1_L08_P1199" (solid, pour order 1199): 142.962,236.744 143.712,237.494 159.212,237.494 159.962,236.744 159.962,227.744 159.212,226.994 143.712,226.994 142.962,227.744
NetNMOS5_1 on L8 "NETNMOS5_1_L08_P1198" (solid, pour order 1198): 97.451,36.055 98.701,37.305 108.701,37.305 109.701,36.055 106.188,26.048 106.188,20.098 105.389,19.299 98.463,19.299 97.451,20.311
NetNMOS4_1 on L8 "NETNMOS4_1_L08_P1197" (solid, pour order 1197): 97.451,106.805 98.701,108.055 108.701,108.055 109.701,106.805 106.188,96.798 106.188,90.848 105.389,90.049 98.463,90.049 97.451,91.061
NetNMOS3_1 on L8 "NETNMOS3_1_L08_P1196" (solid, pour order 1196): 97.451,177.805 98.701,179.055 108.701,179.055 109.701,177.805 106.188,167.798 106.188,161.848 105.389,161.049 98.463,161.049 97.451,162.061
NetNMOS2_1 on L8 "NETNMOS2_1_L08_P1195" (solid, pour order 1195): 97.701,245.805 98.951,247.055 108.951,247.055 109.951,245.805 106.438,235.798 106.438,229.848 105.639,229.049 98.713,229.049 97.701,230.061
GND on L8 "GND_L08_P1194" (solid, pour order 1194): 97.52,323.342 98.52,324.342 168.67,324.342 169.67,323.342 169.67,319.292 165.77,314.342 127.351,314.355 126.66,313.663 126.66,307.322 126.4,306.962 122.637,306.962 114.387,317.342 98.52,317.342 97.52,318.342
NetC12_1 on L8 "NETC12_1_L08_P1193" (solid, pour order 1193): 127.051,311.427 127.651,312.177 134.078,312.177 140.828,312.177 141.578,311.427 141.578,303.177 141.578,294.427 141.078,293.927 130.078,293.927 129.578,294.427 129.578,296.427 129.578,300.677 127.051,304.155
no net on L8 "NONET_L08_P1192" (solid, pour order 1192): 103.328,330.777 102.828,330.777
NetC121_1 on L8 "NETC121_1_L08_P1191" (solid, pour order 1191): 142.947,26.373 143.697,27.123 159.197,27.123 159.947,26.373 159.947,17.373 159.197,16.623 143.697,16.623 142.947,17.373
NetC11_1 on L8 "NETC11_1_L08_P1190" (solid, pour order 1190): 142.578,304.927 143.328,305.677 158.828,305.677 159.578,304.927 159.578,295.927 158.828,295.177 143.328,295.177 142.578,295.927
NetNMOS1_1 on L8 "NETNMOS1_1_L08_P1189" (solid, pour order 1189): 97.701,313.805 98.951,315.055 108.951,315.055 109.951,313.805 106.438,303.798 106.438,297.848 105.639,297.049 98.713,297.049 97.701,298.061
NetC2_1 on L8 "L1-NetC2_1" (solid, pour order 1181): 296.198,327.873 298.202,325.869 373.698,325.869 375.702,327.873 375.702,345.427 365.427,355.702 298.202,355.702 296.198,353.698
NetD17_4 on L8 "NETD17_4_L08_P1153" (solid, pour order 1153): 235.889,56.443 237.901,58.455 271.375,58.455 273.85,56.443 273.85,23.75 271.375,21.449 237.595,21.449 235.889,23.155
NetD13_4 on L8 "NETD13_4_L08_P1152" (solid, pour order 1152): 235.888,126.576 237.9,128.587 271.374,128.587 273.849,126.576 273.849,93.883 271.374,91.582 237.594,91.582 235.888,93.287
NetD9_4 on L8 "NETD9_4_L08_P1151" (solid, pour order 1151): 235.938,196.776 237.95,198.787 271.424,198.787 273.899,196.776 273.899,164.083 271.424,161.782 237.644,161.782 235.938,163.487
NetD5_4 on L8 "NETD5_4_L08_P1150" (solid, pour order 1150): 236.139,266.907 238.151,268.918 271.625,268.918 274.1,266.907 274.1,234.214 271.625,231.912 237.845,231.912 236.139,233.618
NetD1_4 on L8 "NETD1_4_L08_P1149" (solid, pour order 1149): 235.914,339.082 237.926,341.093 271.4,341.093 273.875,339.082 273.875,306.389 271.4,304.087 237.62,304.087 235.914,305.793
GND on L8 "L5-+PH2" (solid, pour order 1148): 23 vertices, not listed, extent 216.154,1.167 365.507,75.312
+PH5 on L8 "L5-+PH2" (solid, pour order 1147): 26 vertices, not listed, extent 216.012,45.175 365.7,145.375
+PH4 on L8 "L5-+PH2" (solid, pour order 1146): 25 vertices, not listed, extent 216.229,115.248 365.583,215.427
+PH3 on L8 "L5-+PH2" (solid, pour order 1145): 26 vertices, not listed, extent 216.102,185.45 365.456,285.629
+PH2 on L8 "L5-+PH2" (solid, pour order 1144): 26 vertices, not listed, extent 215.95,255.519 365.304,355.698
NetD17_1 on L8 "L1-+PH2" (solid, pour order 1023): 257.85,16.987 257.85,8.336 255.85,6.438 217.9,6.438 216.002,8.336 216.002,38.835 218.002,40.835 227.2,40.835 228.752,39.284 228.752,21.086 230.85,18.987 255.85,18.987
NetD13_1 on L8 "L1-+PH2" (solid, pour order 1022): 257.6,87.187 257.6,78.536 255.6,76.638 217.65,76.638 215.752,78.536 215.752,109.035 217.752,111.035 226.95,111.035 228.502,109.484 228.502,91.286 230.6,89.187 255.6,89.187
NetD9_1 on L8 "L1-+PH2" (solid, pour order 1021): 257.65,157.387 257.65,148.736 255.65,146.838 217.7,146.838 215.802,148.736 215.802,179.235 217.802,181.235 227,181.235 228.552,179.684 228.552,161.486 230.65,159.387 255.65,159.387
NetD5_1 on L8 "L1-+PH2" (solid, pour order 1020): 257.85,227.487 257.85,219.117 255.85,217.117 218.002,217.117 216.002,219.117 216.002,249.335 218.002,251.335 227.2,251.335 228.752,249.784 228.752,231.586 230.85,229.487 255.85,229.487
NetD1_1 on L8 "L1-+PH2" (solid, pour order 975): 257.7,299.738 257.7,291.086 255.7,289.188 217.75,289.188 215.852,291.086 215.852,319.237 217.75,321.136 227.2,321.136 228.649,319.687 228.602,303.836 230.7,301.737 255.7,301.737
GND on L5(GND) "GND_L05_P1218" (solid, pour order 1218): 19 vertices, not listed, extent 0.3,0.3 381.825,369.55

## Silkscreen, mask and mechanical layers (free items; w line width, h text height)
Top Overlay:
  drawing of 51 lines, arcs and shapes, not listed
  text "+ 12V -" at 13.05,365.8 h2
  text "+  IN  -" at 85.8,365.8 h2
  text "+  OUT  -" at 378.3,332.2 h2 r270
  text "x" at 315.498,12.918 h4
  text "High-Power Interleaved Forward Converter" at 290.477,8.68 h1.75
  text "Designed by Kane Kyer & Costanza Di Fino" at 300.652,5.513 h1.25
Bottom Overlay:
  drawing of 771 lines, arcs and shapes, not listed
  text "THANK YOU" at 320.546,19.004 h1.52
  text "PROF. NOETSCHER" at 324.721,16.204 h1.52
